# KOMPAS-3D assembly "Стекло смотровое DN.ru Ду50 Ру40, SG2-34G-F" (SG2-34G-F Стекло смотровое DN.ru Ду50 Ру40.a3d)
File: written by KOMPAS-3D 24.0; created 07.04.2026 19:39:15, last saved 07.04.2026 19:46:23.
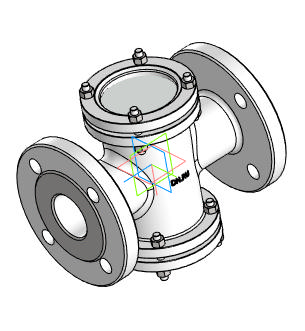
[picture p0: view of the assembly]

Document properties: Автор: Main; Полное имя файла: D:\DN.ru Аутсерс\Стекло смотровое DN.ru\Исходники\Стекло смотровое DN.ru SG2-34G-F тип В ГОСТ 21836-2021 Ду50 Ру40, углеродистая сталь, фланцевое\SG2-34G-F Стекло смотровое DN.ru Ду50 Ру40.a3d

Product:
- Component [detail]: Деталь  | qty 1  | pos. 1  | Масса: 10.795401; Автор: Main; additional columns: Типовые; source file: ДетальДеталь.m3d
- Component [detail]: Стекло  | qty 2  | pos. 2  | Масса: 0.331901; Автор: Main; source file: СтеклоСтекло.m3d
- Component [detail]: ANSI B18.2.4.2M - M8x1,25 - 13  | designation ANSI B18.2.4.2M - M8x1,25  | qty 16  | pos. 3  | Масса: 0.006562; Комментарий: Типы метрических   шестигранных гаек   2; Автор: Main; additional columns: Сталь, мягкая; source file: ANSI B18.2.4.2M - M8x1,25ANSI B18.2.4.2M - M8x1,25 - 13.m3d
- Part/product: Стекло смотровое DN.ru Ду50 Ру40  | designation SG2-34G-F
    Масса: 10.5
    Раздел спецификации: Прочие изделия
    Примечание: D500-00084

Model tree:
1. Массив по концентрической сетке:1  (labels: Грань.Твердое тело1; Ребро.Твердое тело1; Ребро.Solid1; Грань.Solid1)  (4 pattern instances)
     Шаг 2 = 360

Expressions: SG2-34G-F
Referenced files in D:\DN.ru Аутсерс\Стекло смотровое DN.ru\Исходники\Стекло смотровое DN.ru SG2-34G-F тип В ГОСТ 21836-2021 Ду50 Ру40, углеродистая сталь, фланцевое\: ДетальДеталь.m3d, СтеклоСтекло.m3d, ANSI B18.2.4.2M - M8x1,25ANSI B18.2.4.2M - M8x1,25 - 13.m3d
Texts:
  Стекло Стекло (1)
  Стекло Стекло (2)
  ANSI B18.2.4.2M - M8x1,25 ANSI B18.2.4.2M - M8x1,25 - 13 (1)
  ANSI B18.2.4.2M - M8x1,25 ANSI B18.2.4.2M - M8x1,25 - 13 (2)
  ANSI B18.2.4.2M - M8x1,25 ANSI B18.2.4.2M - M8x1,25 - 13 (3)
  ANSI B18.2.4.2M - M8x1,25 ANSI B18.2.4.2M - M8x1,25 - 13 (4)
  ANSI B18.2.4.2M - M8x1,25 ANSI B18.2.4.2M - M8x1,25 - 13 (5)
  ANSI B18.2.4.2M - M8x1,25 ANSI B18.2.4.2M - M8x1,25 - 13 (6)
  ANSI B18.2.4.2M - M8x1,25 ANSI B18.2.4.2M - M8x1,25 - 13 (7)
  ANSI B18.2.4.2M - M8x1,25 ANSI B18.2.4.2M - M8x1,25 - 13 (8)
  ANSI B18.2.4.2M - M8x1,25 ANSI B18.2.4.2M - M8x1,25 - 13 (9)
  ANSI B18.2.4.2M - M8x1,25 ANSI B18.2.4.2M - M8x1,25 - 13 (10)
  ANSI B18.2.4.2M - M8x1,25 ANSI B18.2.4.2M - M8x1,25 - 13 (11)
  ANSI B18.2.4.2M - M8x1,25 ANSI B18.2.4.2M - M8x1,25 - 13 (12)
  ANSI B18.2.4.2M - M8x1,25 ANSI B18.2.4.2M - M8x1,25 - 13 (13)
  ANSI B18.2.4.2M - M8x1,25 ANSI B18.2.4.2M - M8x1,25 - 13 (14)
  ANSI B18.2.4.2M - M8x1,25 ANSI B18.2.4.2M - M8x1,25 - 13 (15)
  ANSI B18.2.4.2M - M8x1,25 ANSI B18.2.4.2M - M8x1,25 - 13 (16)
  Ось Z.Начало координат
  Ось X.Начало координат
